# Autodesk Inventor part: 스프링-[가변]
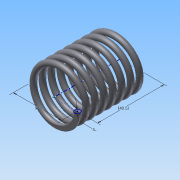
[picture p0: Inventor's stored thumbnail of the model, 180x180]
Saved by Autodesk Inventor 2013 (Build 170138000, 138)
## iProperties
Created: 2015-01
Part Number: 스프링-[가변]
Material: 탄소강
Document SubType Name: Modeling
Designer: user11
Density: 7.87 g/cm^3
Mass: 80.1205 g
Surface Area: 103 cm^2
Volume: 10.1805 cm^3
Author: user11
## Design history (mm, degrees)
sketch "스케치1"
  geometry: L1 (0, 0)-(17.5, 0); L2 (17.5, 0)-(17.5, 48.5); L3 (17.5, 48.5)-(0, 48.5); L4 (0, 48.5)-(0, 0); C1 r 2 at (17.5, 0); 1 further point
  constraints: 8 end point, 2 coincident, 2 parallel, 1 centre point, 1 horizontal, 1 perpendicular
  dimensions: "d0" = 4 diameter of C1; "d1" = 35 diameter of L2 L4; "d2" = 48.5 distance of L1.end L2.end (derived)
feature "코일1" sketch "스케치1" pitch "d3" = 10; turns "d5" = 7.5; dims "d4" = 48.5 (= d2), "d6" = 0, angle "d7" = 90 deg, angle "d8" = 90 deg, "d9" = 0, "d10" = 0
sketch "스케치2"
  geometry: L1 (-19.5, 0)-(-15.5, 0) reference; 1 further point
  constraints: 1 horizontal alignment
extrude "돌출1" cut sketch "스케치2" stored distance "d11" = 10; taper "d12" = 0 deg
node "작업 평면1"
sketch "스케치3"
  geometry: L1 (-4, 0)-(0, 0) reference; 1 further point
  constraints: 1 horizontal alignment
extrude "돌출2" cut sketch "스케치3" stored distance "d13" = 10; taper "d14" = 0 deg
node "솔리드1"
node "절단 모서리 투영1"
node "절단 모서리 투영2"
